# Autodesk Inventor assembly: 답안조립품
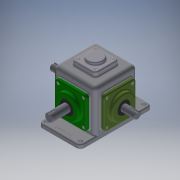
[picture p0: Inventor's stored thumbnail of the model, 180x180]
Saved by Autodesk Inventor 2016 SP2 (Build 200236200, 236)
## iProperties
Created: 2018-09
Part Number: 답안조립품
Document SubType Name: Assembly
Designer: Administrator
Author: Administrator
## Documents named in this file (15)
- Z:\ATC마스터자격증시험\380907V1017 김영호\380907V1017\답안조립품.iam
- Z:\ATC마스터자격증시험\380907V1017 김영호\380907V1017\본체.ipt
- Z:\ATC마스터자격증시험\380907V1017 김영호\380907V1017\메인커버.ipt
- Z:\ATC마스터자격증시험\380907V1017 김영호\380907V1017\서브커버.ipt
- Z:\ATC마스터자격증시험\380907V1017 김영호\380907V1017\베어링 6204.ipt
- Z:\ATC마스터자격증시험\380907V1017 김영호\380907V1017\베어링 6203.ipt
- Z:\ATC마스터자격증시험\380907V1017 김영호\380907V1017\메인축.ipt
- Z:\ATC마스터자격증시험\380907V1017 김영호\380907V1017\키 4x4.ipt
- Z:\ATC마스터자격증시험\380907V1017 김영호\380907V1017\메인베벨기어.ipt
- Z:\ATC마스터자격증시험\380907V1017 김영호\380907V1017\오일 실 20 35 8.ipt
- Z:\ATC마스터자격증시험\380907V1017 김영호\380907V1017\서브베벨기어.ipt
- Z:\ATC마스터자격증시험\380907V1017 김영호\380907V1017\오일 실 17 32 8.ipt
- Z:\ATC마스터자격증시험\380907V1017 김영호\380907V1017\상부커버.ipt
- Z:\ATC마스터자격증시험\380907V1017 김영호\380907V1017\서브축.ipt
- Z:\ATC마스터자격증시험\380907V1017 김영호\380907V1017\볼트 M4.ipt
